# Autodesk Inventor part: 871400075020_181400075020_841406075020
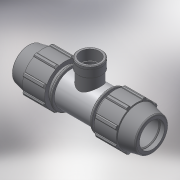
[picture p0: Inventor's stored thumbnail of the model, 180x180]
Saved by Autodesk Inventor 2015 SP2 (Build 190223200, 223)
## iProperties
Created: 2017-02
Part Number: 871400075020_181400075020_841406075020
Material: Generic
Description: PLASSON TEE WITH THREADED FEMALE OFFTAKE 75-2"-75
Document SubType Name: Modeling
Designer: KIM
Mass: 92.6774 g
Surface Area: 199.44 cm^2
Volume: 66.1981 cm^3
Density: 1 g/cm^3
Appearance: Default
Author: KIM
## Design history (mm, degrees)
derived "87140.ipt"
feature "Solid1::87140.ipt"
feature "Solid2::87140.ipt"
tag "TaggingFeature1"
body "Solid1"
other parameters: "d2" = 75, "d4" = 15.41667, "d5" = 44.4, "d7" = 132, "d11" = 6.16667, "d13" = 120 deg, "d14" = 97.5, "d15" = 12 deg, "d16" = 114.84, "d18" = 3.75, "d19" = 35 deg, "d20" = 17.5 deg, "d21" = 122.76, "d23" = 0, "d25" = 360 deg, "d27" = 2.64, "d33" = 1.5, "d42" = 66.6, "d43" = 3.96, "d46" = 2.25, "d68" = 11.1, "d76" = 56.656, "d80" = 1.69968, "d91" = 99, "d93" = 137, "d95" = 67.5, "d115" = 70.82, "d116" = 135 deg, "d117" = 65.1544, "d119" = 67.5, "d121" = 0, "d122" = 50.625, "d124" = 0, "d128" = 0, "d129" = 7.5, "d130" = 9, "d131" = 0.3, "d132" = 0.3, "d133" = 70.82, "d_" = 75, "E_" = 132, "l_" = 137, "Rp_" = 56.656
